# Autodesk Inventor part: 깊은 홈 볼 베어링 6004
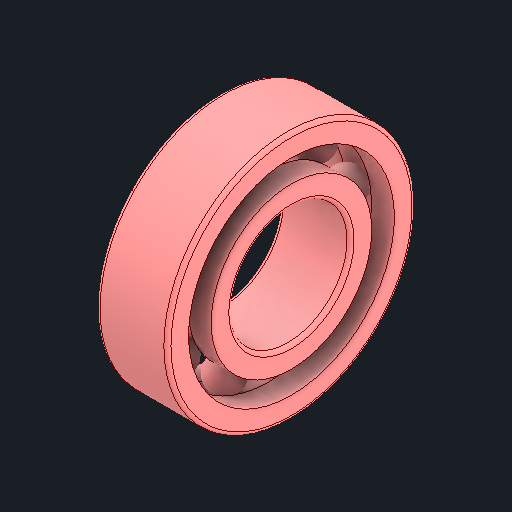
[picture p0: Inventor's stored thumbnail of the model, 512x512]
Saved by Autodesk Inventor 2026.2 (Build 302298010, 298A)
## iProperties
Created: 2026-03
Part Number: 깊은 홈 볼 베어링 6004
Material: 강철, 연강
Description: 깊은 그루브 볼 베어링
Document SubType Name: Modeling
Designer: PC2-02
Density: 7.85 g/cm^3
Appearance: 기본값
Author: jhkim
Sending System: Autodesk Inventor 2026
Preprocessor: ST-DEVELOPER v20.1
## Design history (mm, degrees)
feature "Solid1"
feature "Solid1:1"
feature "Solid1:2"
feature "Solid1:3"
feature "Solid1:4"
feature "Solid1:5"
feature "Solid1:6"
feature "Solid1:7"
feature "Solid1:8"
feature "Solid1:9"
feature "Solid1:10"
node "솔리드1"
node "솔리드2"
node "솔리드3"
node "솔리드4"
node "솔리드5"
node "솔리드6"
node "솔리드7"
node "솔리드8"
node "솔리드9"
node "솔리드10"
node "솔리드11"
